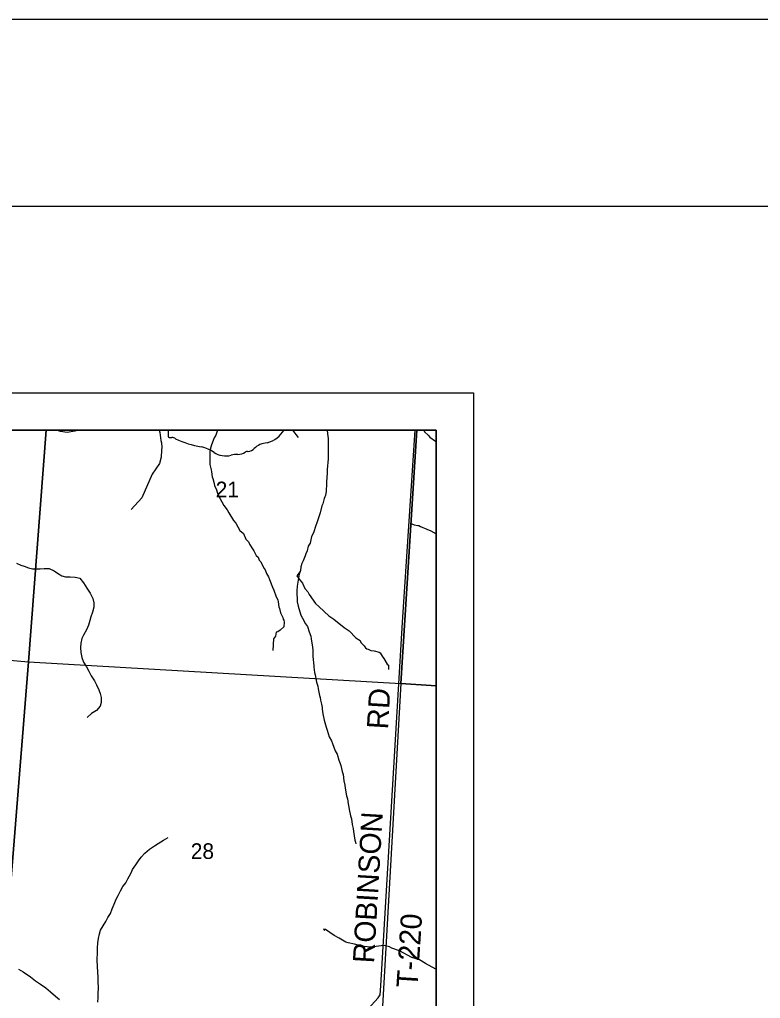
# Model space of a CAD drawing. Extents: x 0 to 34, y 0 to 22.
# Drawn here: x 7.784 to 9.769, y 19.378 to 22 of the extents above; entities that cross this region are included whole.
import ezdxf

# ---------------------------------------------------------------- set-up
doc = ezdxf.new("R2010")
doc.units = 0
for name, color, linetype in [('GM_X_Corporation', 7, 'Continuous'), ('GM_X_Major_Lake_Text', 7, 'Continuous'), ('GM_X_Minor_River', 7, 'Continuous'), ('GM_X_Section_Text', 7, 'Continuous'), ('GM_X_Township_Road', 7, 'Continuous'), ('GM_X_Township_Road_Text', 7, 'Continuous'), ('SH_Border', 7, 'Continuous'), ('SH_Cut_Line', 7, 'Continuous'), ('SH_Data', 7, 'Continuous')]:
    doc.layers.add(name, color=color, linetype=linetype)

msp = doc.modelspace()

# ---------------------------------------------------------------- linework, layer by layer
at = {"layer": 'GM_X_Corporation'}
for p, q in [((8.9, 20.9), (4.9122, 20.9)), ((7.798, 20.9), (6.7774, 20.9)), ((8.7877, 20.9), (7.798, 20.9)), ((8.9, 20.9), (8.7877, 20.9)), ((8.9, 19.9935), (8.9, 20.9)), ((8.9, 18.0235), (8.9, 20.9)), ((8.9, 19.0688), (8.9, 19.9935))]:
    msp.add_line(p, q, dxfattribs=at)
msp.add_lwpolyline([(6.4848, 18.4217), (8.9, 18.2459), (8.9, 20.9), (4.892, 20.9)], dxfattribs=at)
for points in [[(7.8557, 20.9), (6.8372, 20.9), (6.802, 20.3679), (7.8088, 20.2797)], [(8.8483, 20.9), (7.8557, 20.9), (7.8088, 20.2797), (8.8059, 20.2218)], [(8.9, 20.2153), (8.9, 20.9), (8.8483, 20.9), (8.8059, 20.2218)], [(6.802, 20.3679), (7.8088, 20.2797), (7.7331, 19.3433), (6.741, 19.4109)], [(7.8088, 20.2797), (8.8059, 20.2218), (8.7529, 19.294), (7.7331, 19.3433)], [(8.9, 19.2883), (8.9, 20.2153), (8.8059, 20.2218), (8.7529, 19.294)]]:
    msp.add_lwpolyline(points, close=True, dxfattribs=at)
at = {"layer": 'GM_X_Major_Lake_Text'}
msp.add_lwpolyline([(8.4928, 20.9), (8.1825, 20.9), (8.1825, 20.884)], dxfattribs=at)
for centre, major_axis, start_param, end_param in [((8.4143, 20.9307), (0.0874, 0), 5.101753, 5.828817), ((8.1863, 20.8835), (0.00385, 0), 2.993084, 4.5083), ((8.1869, 20.904), (0.0294, 0), 4.665946, 4.897461), ((8.1929, 20.8724), (0.0106, 0), 0.519207, 1.627899), ((8.3268, 21.0522), (0.2524, 0), 4.195997, 4.488961), ((8.2515, 20.7941), (0.079, 0), 0.823519, 1.323587), ((8.3905, 20.8646), (0.0282, 0), 4.937069, 5.64225), ((8.4512, 20.8278), (0.0479, 0), 1.647645, 2.488434), ((8.3369, 20.8714), (0.0501, 0), 4.026481, 4.996735), ((8.3659, 20.8023), (0.0412, 0), 1.495662, 1.94098), ((8.3695, 20.8565), (0.0267, 0), 4.691044, 5.507374), ((8.3937, 20.8371), (0.00752, 0), 1.147584, 2.315152)]:
    msp.add_ellipse(centre, major_axis=major_axis, ratio=0.8, start_param=start_param, end_param=end_param, dxfattribs=at)
at = {"layer": 'GM_X_Minor_River'}
for p, q in [((7.8937, 20.8963), (7.8831, 20.9)), ((7.9324, 20.8975), (7.9119, 20.8938)), ((7.9408, 20.9), (7.9324, 20.8975)), ((8.5158, 20.9), (8.5304, 20.8807)), ((7.9119, 20.8938), (7.8937, 20.8963)), ((8.8303, 20.6514), (8.8413, 20.6467)), ((8.8413, 20.6467), (8.8508, 20.6451)), ((8.8508, 20.6451), (8.8535, 20.6444)), ((8.8535, 20.6444), (8.8581, 20.6424)), ((8.8581, 20.6424), (8.8755, 20.6351)), ((8.8755, 20.6351), (8.8862, 20.6305)), ((8.8862, 20.6305), (8.9, 20.6228))]:
    msp.add_line(p, q, dxfattribs=at)
for points in [[(8.1587, 20.9), (8.1605, 20.8937), (8.1631, 20.8724), (8.165, 20.8659), (8.1657, 20.8549), (8.1649, 20.8469), (8.164, 20.8275), (8.159, 20.8108), (8.1399, 20.7821), (8.1115, 20.7188), (8.0836, 20.6875)], [(8.3144, 20.9), (8.3104, 20.8869), (8.3058, 20.8794), (8.2985, 20.8608), (8.295, 20.8487), (8.2938, 20.8407), (8.2937, 20.8164), (8.2944, 20.8084), (8.2974, 20.7935), (8.2985, 20.7882), (8.3007, 20.7753), (8.3019, 20.7711), (8.3045, 20.7612), (8.306, 20.7566), (8.3067, 20.7517), (8.312, 20.7406), (8.3165, 20.7254), (8.321, 20.7181), (8.3312, 20.6983), (8.3407, 20.6865), (8.3445, 20.6792), (8.3573, 20.6586), (8.3634, 20.651), (8.3743, 20.6315), (8.3838, 20.6231), (8.3906, 20.6086), (8.3981, 20.6002), (8.4004, 20.5948), (8.4083, 20.5819), (8.4117, 20.5769), (8.4185, 20.5643), (8.4234, 20.5597), (8.4264, 20.5517), (8.4302, 20.5471), (8.4348, 20.538), (8.4397, 20.5296), (8.4423, 20.5261), (8.4457, 20.5159), (8.4514, 20.5071), (8.4536, 20.5006), (8.4619, 20.4793), (8.4657, 20.4716), (8.4721, 20.4541), (8.4758, 20.4453), (8.4766, 20.44), (8.4792, 20.4271), (8.4807, 20.4225), (8.4837, 20.4111), (8.4893, 20.3981), (8.4908, 20.3943), (8.4923, 20.3913), (8.4934, 20.3855), (8.4922, 20.373), (8.4827, 20.3647), (8.4762, 20.3602), (8.472, 20.3587), (8.4712, 20.3538), (8.4697, 20.3488), (8.4643, 20.3417), (8.4631, 20.3097)], [(8.6084, 20.9), (8.609, 20.8902), (8.6108, 20.878), (8.6106, 20.8237), (8.6086, 20.7948), (8.6085, 20.7853), (8.6069, 20.7618), (8.6061, 20.7542), (8.6057, 20.7397), (8.6053, 20.7363), (8.6045, 20.7314), (8.6037, 20.7249), (8.6018, 20.7215), (8.6006, 20.7173), (8.5964, 20.7033), (8.5941, 20.6972), (8.5894, 20.679), (8.5871, 20.6711), (8.5805, 20.6517), (8.5775, 20.6445), (8.5713, 20.6256), (8.5659, 20.6157), (8.5624, 20.5971), (8.5578, 20.5892), (8.5547, 20.5767), (8.5509, 20.5687), (8.5497, 20.5634), (8.5444, 20.5498), (8.5405, 20.5429), (8.5374, 20.5338), (8.5366, 20.5247), (8.5336, 20.5145), (8.5277, 20.4826), (8.5269, 20.4701), (8.5279, 20.44), (8.5305, 20.429), (8.5376, 20.4046), (8.5422, 20.397), (8.5501, 20.3814), (8.5558, 20.3745), (8.5599, 20.3596), (8.5644, 20.3486), (8.5655, 20.3413), (8.5692, 20.3193), (8.57, 20.3113), (8.5699, 20.293), (8.5706, 20.287), (8.5713, 20.2759), (8.5721, 20.2695), (8.5724, 20.2653), (8.5743, 20.2512), (8.5757, 20.2444), (8.5795, 20.2253), (8.5828, 20.2147), (8.584, 20.2074), (8.5877, 20.1899), (8.5896, 20.1838), (8.5907, 20.1766), (8.5933, 20.1659), (8.5948, 20.1576), (8.5951, 20.153), (8.5966, 20.1408), (8.6003, 20.1237), (8.6052, 20.1047), (8.6082, 20.0963), (8.6138, 20.0784), (8.6202, 20.0677), (8.6225, 20.0609), (8.63, 20.041), (8.6353, 20.0326)], [(8.8668, 20.9), (8.8692, 20.8956), (8.8786, 20.8868), (8.8828, 20.8818), (8.898, 20.8707), (8.9, 20.8699)], [(7.7761, 20.5436), (7.7875, 20.539), (7.797, 20.5356), (7.808, 20.5318), (7.819, 20.5287), (7.8293, 20.5287), (7.8395, 20.5291), (7.8502, 20.5294), (7.8638, 20.5294), (7.8767, 20.5237), (7.8862, 20.5168), (7.8976, 20.5103), (7.9071, 20.5077), (7.92, 20.5069), (7.9337, 20.5065), (7.9458, 20.5038), (7.9561, 20.4909), (7.9648, 20.4768), (7.9735, 20.4638), (7.9807, 20.449), (7.9833, 20.438), (7.9833, 20.4262), (7.9799, 20.4129), (7.9749, 20.4), (7.9722, 20.3905), (7.9688, 20.378), (7.9634, 20.3658), (7.9558, 20.3514), (7.9513, 20.3419), (7.9486, 20.3298), (7.9478, 20.3184), (7.9489, 20.3043), (7.9515, 20.2914), (7.9561, 20.2784), (7.9637, 20.2659), (7.9697, 20.2545), (7.9762, 20.2419), (7.9849, 20.2286), (7.9905, 20.218), (7.997, 20.2046), (8.0004, 20.1948), (8.0026, 20.1845), (8.003, 20.1708), (8.0003, 20.1609), (7.9908, 20.1496), (7.9775, 20.1412), (7.9653, 20.1302)], [(8.5357, 20.5216), (8.5267, 20.5103), (8.5331, 20.5008), (8.5418, 20.4901), (8.5482, 20.476), (8.5569, 20.4668), (8.5596, 20.4596), (8.5766, 20.4359), (8.5872, 20.4267), (8.6126, 20.403), (8.6262, 20.3941), (8.6539, 20.3719), (8.6672, 20.3627), (8.6853, 20.3435), (8.6963, 20.337), (8.6986, 20.3317), (8.7069, 20.3229), (8.7111, 20.3171), (8.7149, 20.3148), (8.7183, 20.3137), (8.7248, 20.3102), (8.7343, 20.309), (8.7472, 20.3059), (8.7498, 20.304), (8.7559, 20.2948), (8.7604, 20.2883), (8.7691, 20.273), (8.7725, 20.2711), (8.7728, 20.2593)], [(8.6353, 20.0326), (8.6394, 20.0166), (8.6432, 20.0075), (8.6447, 20.0018), (8.6484, 19.9858), (8.6507, 19.9778), (8.6525, 19.9611), (8.6555, 19.9489), (8.6566, 19.9409), (8.6599, 19.9211), (8.6626, 19.9131), (8.6644, 19.8994), (8.6666, 19.8903), (8.6674, 19.8842), (8.6707, 19.8671), (8.6734, 19.8595), (8.6752, 19.8439), (8.6782, 19.8328), (8.6789, 19.8248), (8.6826, 19.802), (8.6845, 19.7963), (8.6849, 19.7925)], [(7.9937, 19.3683), (7.9948, 19.3804), (7.9952, 19.3911), (7.9956, 19.4066), (7.9949, 19.423), (7.9945, 19.4351), (7.9942, 19.4484), (7.9935, 19.4636), (7.9927, 19.4804), (7.9928, 19.5024), (7.9932, 19.513), (7.9943, 19.5271), (7.9955, 19.5385), (7.9982, 19.551), (8.0012, 19.5609), (8.0081, 19.5727), (8.0153, 19.5844), (8.021, 19.5951), (8.0279, 19.6053), (8.0325, 19.6182), (8.0382, 19.6304), (8.0431, 19.6437), (8.0485, 19.6539), (8.0546, 19.6661), (8.0614, 19.6775), (8.0687, 19.6873), (8.0744, 19.6983), (8.0831, 19.7143), (8.0873, 19.7238), (8.0957, 19.7355), (8.1033, 19.7466), (8.1098, 19.756), (8.1197, 19.7674), (8.1326, 19.778), (8.1455, 19.7864), (8.1554, 19.7932), (8.1699, 19.8023), (8.1828, 19.8095)], [(8.9, 19.4558), (8.8994, 19.4566), (8.8713, 19.4716), (8.8558, 19.4812), (8.8353, 19.4879), (8.8019, 19.5059), (8.7814, 19.5125), (8.7753, 19.516), (8.7609, 19.5195), (8.7525, 19.5188), (8.7319, 19.5159), (8.722, 19.5156), (8.7186, 19.5156), (8.7152, 19.516), (8.7072, 19.5172), (8.7008, 19.5181), (8.6818, 19.5231), (8.6647, 19.5267), (8.6586, 19.5286), (8.6407, 19.5394), (8.6271, 19.5467), (8.6036, 19.5624), (8.5986, 19.5632), (8.6024, 19.5613)], [(7.7815, 19.456), (7.7944, 19.4492), (7.8138, 19.4358), (7.8274, 19.4248), (7.8403, 19.4164), (7.8551, 19.4061), (7.8672, 19.3958), (7.8805, 19.384), (7.8911, 19.3749)]]:
    msp.add_lwpolyline(points, dxfattribs=at)
at = {"layer": 'GM_X_Township_Road'}
msp.add_lwpolyline([(8.662, 19.2932), (8.6992, 19.33), (8.7448, 19.38), (8.7499, 19.3875), (8.7519, 19.4118), (8.8097, 20.3858), (8.8436, 20.9)], dxfattribs=at)
at = {"layer": 'SH_Border'}
msp.add_lwpolyline([(1.5, 21.5), (33.5, 21.5), (33.5, 0.5), (1.5, 0.5)], close=True, dxfattribs=at)
at = {"layer": 'SH_Cut_Line'}
msp.add_lwpolyline([(0, 0), (34, 0), (34, 22), (0, 22)], close=True, dxfattribs=at)
at = {"layer": 'SH_Data'}
for p, q in [((2, 21), (9, 21)), ((9, 21), (9, 14)), ((2.1, 20.9), (8.9, 20.9)), ((8.9, 20.9), (8.9, 14.1))]:
    msp.add_line(p, q, dxfattribs=at)

# ---------------------------------------------------------------- texts
at = {"layer": 'GM_X_Section_Text'}
for s, p in [('21', (8.3097, 20.7204)), ('28', (8.243, 19.7517))]:
    msp.add_text(s, height=0.04186, rotation=0, dxfattribs=at).set_placement(p)
at = {"layer": 'GM_X_Township_Road_Text'}
for s, rotation, p in [('RD', 86.5467, (8.7711, 20.098)), ('ROBINSON', 86.6412, (8.7336, 19.4713)), ('T-220', 86.3546, (8.8502, 19.4054))]:
    msp.add_text(s, height=0.05682, rotation=rotation, dxfattribs=at).set_placement(p)

doc.saveas('drawing.dxf')
